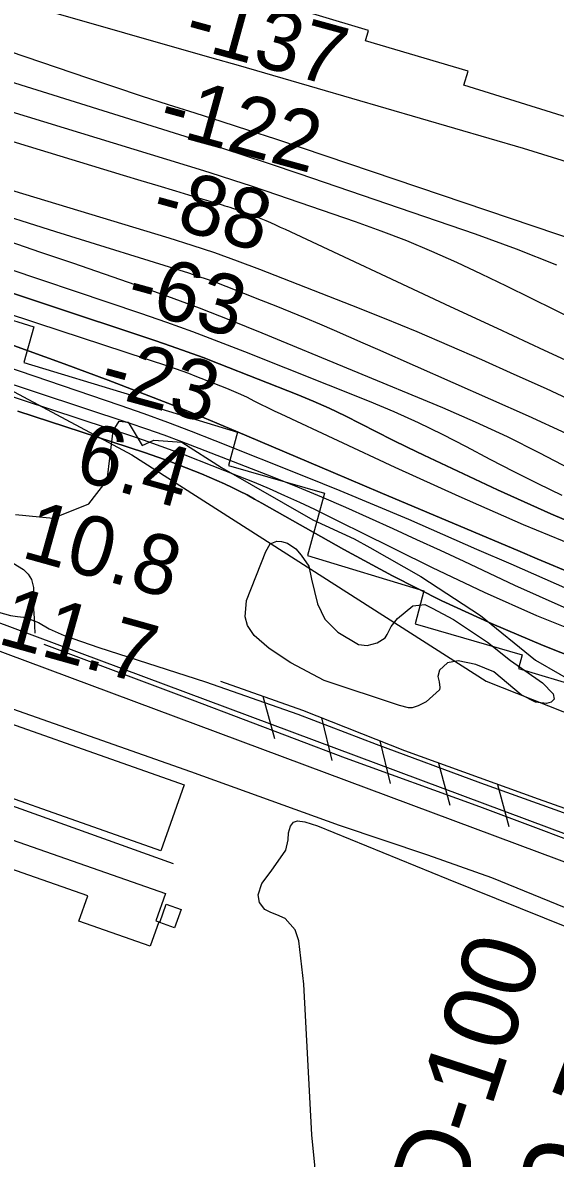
# Model space of a CAD drawing. Extents: x 3715084 to 3753216, y 488173 to 513963.
# Drawn here: x 3726412 to 3727006, y 497978 to 499247 of the extents above; entities that cross this region are included whole.
import ezdxf

# ---------------------------------------------------------------- set-up
doc = ezdxf.new("R2010")
doc.units = 0
for name, color, linetype in [('V-BLDG-OTLN', 7, 'Continuous'), ('V-FLOD-BASE', 7, 'Continuous'), ('V-LEVE-TOET', 7, 'Continuous'), ('V-RIVR-EDGE', 7, 'Continuous'), ('V-RIVR-RANG', 7, 'Continuous'), ('V-RIVR-RANG-IDEN', 7, 'Continuous'), ('V-ROAD-CNTR', 7, 'Continuous'), ('V-RRAP-FSHR', 7, 'Continuous'), ('V-RRAP-RVMT', 7, 'Continuous'), ('V-SITE-VEGE', 7, 'Continuous'), ('V-SURV-IDEN', 7, 'Continuous'), ('V-SURV-LINE', 7, 'Continuous'), ('V-TOPO-DPTH', 7, 'Continuous'), ('V-TOPO-MAJR', 7, 'Continuous'), ('V-TOPO-MINR', 7, 'Continuous'), ('V-TOPO-WATR', 7, 'Continuous')]:
    doc.layers.add(name, color=color, linetype=linetype)

msp = doc.modelspace()

# ---------------------------------------------------------------- linework, layer by layer
at = {"layer": 'V-BLDG-OTLN'}
for points in [[(3726309.3, 498495.2), (3726591.9, 498395.2), (3726565.9, 498321.6), (3726283.2, 498421.5)], [(3726554.1, 498215), (3726474.5, 498242.9), (3726484.5, 498271.3), (3726389.8, 498304.5), (3726400.1, 498333.9), (3726571.2, 498273.9), (3726560.4, 498243.1), (3726563.6, 498242)], [(3726572.1, 498261.8), (3726588.6, 498256), (3726581.4, 498235.4), (3726564.9, 498241.3)]]:
    msp.add_lwpolyline(points, close=True, dxfattribs=at)
at = {"layer": 'V-FLOD-BASE'}
msp.add_lwpolyline([(3726435.3, 498552.5), (3726601, 498490.1), (3726771.9, 498425.4), (3726921.7, 498371.2), (3727078.5, 498312.3), (3727260.6, 498243.5), (3727360.9, 498203.8), (3727504.7, 498147.2), (3727592.6, 498115.2), (3727705.1, 498073.2), (3727781.8, 498047), (3727820.7, 498036.5), (3727846.6, 498030.7), (3727871.9, 498027.3), (3727937.3, 498021), (3728099.8, 498012.2), (3728258.8, 498002.8)], dxfattribs=at)
at = {"layer": 'V-LEVE-TOET'}
for points in [[(3725953.9, 498750.4), (3725975.8, 498740.8), (3726002.6, 498731.4), (3726033, 498720.9), (3726090.4, 498697.5), (3726197.3, 498655.1), (3726292.1, 498620.8), (3726384.3, 498588.2), (3726398.1, 498584.4), (3726406.1, 498583.3), (3726412.7, 498582.5), (3726416.3, 498581.6)], [(3725958.4, 498636), (3725987.9, 498628), (3726077.6, 498597.4), (3726210.5, 498550.6), (3726367.3, 498491.9), (3726599, 498410), (3726765.2, 498350.1), (3726863.8, 498316.9), (3726935.1, 498291.6), (3727054.7, 498243), (3727151.8, 498206.2), (3727209, 498188.4), (3727242.1, 498172.1), (3727277, 498151.6), (3727309.7, 498134.7), (3727402.2, 498100.1), (3727510.5, 498069), (3727562.5, 498053.8), (3727581.7, 498047.1), (3727583, 498046.7)], [(3726416.3, 498581.6), (3726417.9, 498581), (3726429.4, 498576.8), (3726441.2, 498569.7), (3726458, 498562.2), (3726496.6, 498548.9), (3726615.9, 498510.5), (3726719.1, 498474.2), (3726806.4, 498440.7), (3726923, 498397.5), (3727049.3, 498352), (3727184.7, 498300.4), (3727316.2, 498249.8), (3727404.3, 498215.2), (3727526.4, 498167.7), (3727549, 498158.9)]]:
    msp.add_lwpolyline(points, dxfattribs=at)
at = {"layer": 'V-RIVR-EDGE'}
msp.add_lwpolyline([(3726403.8, 498697.5), (3726445.8, 498693.2), (3726485.5, 498709.3), (3726506, 498735.7), (3726512.7, 498790.9), (3726519.3, 498801.7), (3726529.5, 498800.5), (3726545.1, 498774.6), (3726558.3, 498780.6), (3726589.5, 498778.1), (3726633.9, 498749.8), (3726735.8, 498691.3), (3726781.9, 498670.2), (3726799.3, 498660.5), (3726856.3, 498628), (3726922.8, 498584.6), (3726984.5, 498534.6), (3727038.5, 498503.2)], dxfattribs=at)
at = {"layer": 'V-ROAD-CNTR'}
for points in [[(3726360.1, 498667.8), (3726412.7, 498635.9), (3726418, 498630.8), (3726421.5, 498624.6), (3726423.7, 498615.7), (3726423.6, 498597.1), (3726424.6, 498581.1), (3726425.4, 498564.7)], [(3725893.8, 498553.5), (3726579.6, 498307.2)]]:
    msp.add_lwpolyline(points, dxfattribs=at)
at = {"layer": 'V-RRAP-FSHR'}
for p, q in [((3726679.8, 498494.2), (3726693, 498447.1)), ((3726745.5, 498470.1), (3726756.8, 498422.6)), ((3726810.6, 498444.3), (3726821.9, 498396.8)), ((3726876.1, 498419.6), (3726888.8, 498372.5)), ((3726941.9, 498395.8), (3726954.7, 498348.7))]:
    msp.add_line(p, q, dxfattribs=at)
for points in [[(3719778.9, 501659.5), (3719780.9, 501658.9), (3720162.1, 501439.6), (3720517.2, 501248), (3721025.7, 501011.2), (3721396.9, 500844.8), (3721781.4, 500671.7), (3722343.7, 500424.7), (3722591.4, 500331.7), (3722936.5, 500157.7), (3723365.3, 499935.7), (3724002.2, 499670.3), (3724701.9, 499359), (3725287.2, 499128.8), (3725832.9, 499021), (3726260.1, 498910.4), (3726533.7, 498764.1), (3726929.4, 498511.1), (3727309.4, 498360.7), (3727495.4, 498332.2), (3727633.2, 498290.4), (3727809.2, 498206.8), (3728004.4, 498122.8), (3728249.6, 498078.8)], [(3727308.7, 498256.8), (3727263.5, 498272.8), (3727136.8, 498326.2), (3726987.6, 498379.3), (3726838.5, 498433.2), (3726724.4, 498478.5), (3726632.9, 498510.6)]]:
    msp.add_lwpolyline(points, dxfattribs=at)
at = {"layer": 'V-RRAP-RVMT'}
for p, q in [((3726797.8, 499238.2), (3726677.2, 499274.9)), ((3726794.5, 499226.9), (3726797.8, 499238.2)), ((3726909.1, 499192.7), (3726794.5, 499226.9)), ((3726904.2, 499177.2), (3726909.1, 499192.7)), ((3727031, 499137.7), (3726904.2, 499177.2)), ((3726305.1, 498943.3), (3726424.2, 498907.3)), ((3726424.2, 498907.3), (3726413.2, 498867.1)), ((3726413.2, 498867.1), (3726533.3, 498830.9)), ((3726533.3, 498830.9), (3726531.9, 498825.8)), ((3726531.9, 498825.8), (3726651.6, 498789.5)), ((3726651.6, 498789.5), (3726641.5, 498752.3)), ((3726641.5, 498752.3), (3726748.7, 498721.4)), ((3726748.7, 498721.4), (3726729.7, 498651.5)), ((3726729.7, 498651.5), (3726859.7, 498612)), ((3726859.7, 498612), (3726849.8, 498575.3)), ((3726849.8, 498575.3), (3726969.6, 498540.7)), ((3726969.6, 498540.7), (3726965.5, 498525.3)), ((3726965.5, 498525.3), (3727039.2, 498503))]:
    msp.add_line(p, q, dxfattribs=at)
at = {"layer": 'V-SITE-VEGE'}
msp.add_lwpolyline([(3726877.3, 498501.6), (3726862.4, 498488.2), (3726853.3, 498483.4), (3726846.5, 498481.4), (3726842.7, 498481.2), (3726832.3, 498483.9), (3726748.4, 498511.8), (3726711.1, 498531.7), (3726687, 498547.6), (3726670.2, 498562.3), (3726662.9, 498573.5), (3726660.1, 498583), (3726661.8, 498601.1), (3726683.2, 498656), (3726687.9, 498664.5), (3726695.6, 498667.7), (3726700.7, 498667.1), (3726707.4, 498665.3), (3726716.9, 498659.1), (3726722.7, 498652), (3726731.2, 498639.6), (3726734.4, 498625.2), (3726740.8, 498597.7), (3726749.1, 498580.4), (3726763.6, 498566), (3726786.7, 498552.1), (3726796.3, 498551), (3726807.4, 498553.8), (3726816.6, 498559.5), (3726818.8, 498563.3), (3726823.3, 498572.2), (3726830.3, 498581), (3726847.2, 498595.3), (3726860.6, 498596.7), (3726868.9, 498592.6), (3726892.6, 498580.1), (3726930.7, 498554.8), (3726956.6, 498534.4), (3726992, 498509.1), (3727004.2, 498496.9), (3727005, 498491.2), (3727001.9, 498487.5), (3726996.6, 498486.3), (3726984.2, 498487.6), (3726968.2, 498496), (3726937.7, 498521.7), (3726917.8, 498529.9), (3726897.9, 498533.8), (3726885.9, 498531.8), (3726877.2, 498523.5), (3726875.1, 498516.4), (3726876.7, 498510.3), (3726877.7, 498504)], close=True, dxfattribs=at)
msp.add_lwpolyline([(3726745.2, 497898.8), (3726734.7, 498004), (3726725.6, 498172.4), (3726720.1, 498220.8), (3726715.9, 498233.4), (3726704.9, 498246), (3726695.6, 498250.1), (3726688.7, 498252.5), (3726682, 498256), (3726676.2, 498263.8), (3726674.8, 498272.5), (3726678.7, 498285), (3726689.3, 498298.8), (3726705.4, 498322.3), (3726708.3, 498333.7), (3726708.5, 498341.6), (3726710.8, 498348.9), (3726714.3, 498353.5), (3726718.7, 498354.9), (3726726.7, 498353.9), (3726741.1, 498349.6), (3726886.7, 498290), (3727101.2, 498203.5)], dxfattribs=at)
at = {"layer": 'V-SURV-LINE'}
for points in [[(3725402.7, 498943.3), (3727093.5, 498312.2)], [(3727083, 498284.1), (3725392.3, 498915.2)]]:
    msp.add_lwpolyline(points, dxfattribs=at)
at = {"layer": 'V-TOPO-DPTH'}
for points in [[(3727029, 498630), (3726986.2, 498648), (3726967.3, 498655.9), (3726915.1, 498677.9), (3726862.9, 498700), (3726810.8, 498722.1), (3726758.6, 498744.3), (3726649.9, 498790.6), (3726614.4, 498805.5), (3726578.8, 498819.9), (3726543, 498833.9), (3726507, 498847.4), (3726458, 498865.6), (3726397.3, 498887.7), (3726336.5, 498909.3), (3726275.4, 498930.2), (3726214.2, 498950.8), (3725686.5, 499124.4), (3725658, 499134), (3725629.5, 499144), (3725601.2, 499154.3), (3725573, 499165), (3725377.1, 499241)], [(3727029, 498630), (3726986.2, 498648), (3726967.3, 498655.9), (3726915.1, 498677.9), (3726862.9, 498700), (3726810.8, 498722.1), (3726758.6, 498744.3), (3726649.9, 498790.6), (3726614.4, 498805.5), (3726578.8, 498819.9), (3726543, 498833.9), (3726507, 498847.4), (3726458, 498865.6), (3726397.3, 498887.7), (3726336.5, 498909.3), (3726275.4, 498930.2), (3726214.2, 498950.8), (3725686.5, 499124.4), (3725658, 499134), (3725629.5, 499144), (3725601.2, 499154.3), (3725573, 499165), (3725377.1, 499241)], [(3727061.1, 498672.8), (3727001.3, 498698.3), (3726941.9, 498725), (3726859.5, 498763.7), (3726841.8, 498772.2), (3726824.2, 498780.8), (3726806.7, 498789.7), (3726789.3, 498798.7), (3726771.8, 498807.6), (3726754.1, 498816.1), (3726736.2, 498824), (3726718.1, 498831.5), (3726631, 498865.8), (3726613.2, 498872.7), (3726595.3, 498879.3), (3726577.4, 498885.7), (3726559.3, 498891.8), (3725816.5, 499139)], [(3727061.1, 498672.8), (3727001.3, 498698.3), (3726941.9, 498725), (3726859.5, 498763.7), (3726841.8, 498772.2), (3726824.2, 498780.8), (3726806.7, 498789.7), (3726789.3, 498798.7), (3726771.8, 498807.6), (3726754.1, 498816.1), (3726736.2, 498824), (3726718.1, 498831.5), (3726631, 498865.8), (3726613.2, 498872.7), (3726595.3, 498879.3), (3726577.4, 498885.7), (3726559.3, 498891.8), (3725816.5, 499139)], [(3725709.8, 499071.6), (3726530.2, 498799.9), (3726549.9, 498793.2), (3726569.5, 498786.3), (3726589.1, 498779.1), (3726608.5, 498771.7), (3726691.7, 498739.1), (3726718.7, 498728.3), (3726745.5, 498717.2), (3726772.2, 498705.6), (3726798.7, 498693.8), (3726825.1, 498681.8), (3726851.5, 498669.6), (3726877.9, 498657.4), (3726904.2, 498645.1), (3726961, 498618.6), (3727016, 498593.8)], [(3725709.8, 499071.6), (3726530.2, 498799.9), (3726549.9, 498793.2), (3726569.5, 498786.3), (3726589.1, 498779.1), (3726608.5, 498771.7), (3726691.7, 498739.1), (3726718.7, 498728.3), (3726745.5, 498717.2), (3726772.2, 498705.6), (3726798.7, 498693.8), (3726825.1, 498681.8), (3726851.5, 498669.6), (3726877.9, 498657.4), (3726904.2, 498645.1), (3726961, 498618.6), (3727016, 498593.8)], [(3726347.8, 498937.8), (3726428.3, 498911.3), (3726574.6, 498863.1), (3726582, 498860.6), (3726589.4, 498858), (3726596.8, 498855.2), (3726604.1, 498852.4), (3726639.4, 498838.5), (3726647.1, 498835.3), (3726654.8, 498832), (3726662.4, 498828.4), (3726669.9, 498824.6), (3726677.4, 498820.8), (3726685, 498817.1), (3726692.5, 498813.4), (3726700.1, 498809.8), (3726827.2, 498750.2), (3726898.7, 498717.7), (3726970.6, 498686.2), (3727043.3, 498656.4)], [(3726347.8, 498937.8), (3726428.3, 498911.3), (3726574.6, 498863.1), (3726582, 498860.6), (3726589.4, 498858), (3726596.8, 498855.2), (3726604.1, 498852.4), (3726639.4, 498838.5), (3726647.1, 498835.3), (3726654.8, 498832), (3726662.4, 498828.4), (3726669.9, 498824.6), (3726677.4, 498820.8), (3726685, 498817.1), (3726692.5, 498813.4), (3726700.1, 498809.8), (3726827.2, 498750.2), (3726898.7, 498717.7), (3726970.6, 498686.2), (3727043.3, 498656.4)], [(3727073.6, 498518.9), (3726993, 498551.1), (3726936, 498575.2), (3726879.7, 498600.8), (3726824.6, 498628.8), (3726770.2, 498658.2), (3726678.7, 498710.2), (3726670.5, 498714.7), (3726662.3, 498719.2), (3726654, 498723.5), (3726645.6, 498727.7), (3726637.2, 498731.7), (3726628.7, 498735.5), (3726620.1, 498739.2), (3726611.4, 498742.7), (3726577.3, 498756.1), (3726570, 498758.8), (3726562.7, 498761.5), (3726555.3, 498764.1), (3726547.9, 498766.6), (3726406.4, 498813)]]:
    msp.add_lwpolyline(points, dxfattribs=at)
at = {"layer": 'V-TOPO-MAJR'}
for points in [[(3726031.1, 499260.8), (3726139.6, 499227.1), (3726248.1, 499193.6), (3726356.7, 499160.3), (3726613.5, 499081.8), (3726631, 499076.3), (3726648.4, 499070.8), (3726665.8, 499065), (3726683.1, 499059.2), (3726783, 499024.8), (3726811.7, 499014.4), (3726840.2, 499003.5), (3726868.3, 498991.7), (3726896.2, 498979.3), (3726923.8, 498966.3), (3726951.4, 498953.1), (3726978.8, 498939.7), (3727006.1, 498926), (3727045.3, 498906.2)], [(3725591.6, 499253.3), (3725625.1, 499240.2), (3725658.6, 499227.3), (3725692.4, 499214.8), (3725726.2, 499202.6), (3725830.6, 499165.5), (3725916.8, 499135.2), (3726003.1, 499105.1), (3726089.5, 499075.4), (3726176, 499046), (3726543.2, 498922.4), (3726572.4, 498912.3), (3726601.5, 498901.9), (3726630.5, 498890.9), (3726659.3, 498879.7), (3726798.5, 498824.1), (3726826.1, 498812.5), (3726853.4, 498800.2), (3726880.3, 498787.1), (3726906.9, 498773.3), (3726933.4, 498759.2), (3726960, 498745.4), (3726986.9, 498732.1), (3727013.8, 498718.9)]]:
    msp.add_lwpolyline(points, dxfattribs=at)
at = {"layer": 'V-TOPO-MINR'}
for points in [[(3725245.4, 499590.8), (3725645.7, 499429.6), (3725682.4, 499415.1), (3725719.3, 499400.9), (3725756.3, 499387.2), (3725793.5, 499373.9), (3725830.8, 499360.9), (3725868.2, 499348.3), (3725905.8, 499336), (3725943.4, 499324), (3726592.7, 499120.3), (3726624.6, 499110.2), (3726656.5, 499099.8), (3726688.2, 499089.3), (3726719.9, 499078.5), (3726916.9, 499010.9), (3726962.6, 498994.2), (3727007.9, 498976.3)], [(3725373.4, 499579.9), (3725463.2, 499544.7), (3725553.2, 499510.1), (3725691.8, 499457.2), (3725712.7, 499449.4), (3725733.5, 499441.7), (3725754.5, 499434.3), (3725775.5, 499427), (3726484.2, 499185.3), (3726514.1, 499175.3), (3726544, 499165.4), (3726574, 499155.7), (3726604, 499146.2), (3726634, 499136.6), (3726664, 499127), (3726693.9, 499117.1), (3726723.8, 499107.1), (3727059.7, 498993.4)], [(3725378.1, 499360), (3725474.1, 499323.1), (3725622, 499266.6), (3725644.2, 499258.2), (3725666.6, 499250.1), (3725689, 499242.1), (3725711.5, 499234.4), (3726396.1, 499002.7), (3726431.6, 498990.6), (3726467.2, 498978.5), (3726502.7, 498966.3), (3726538.2, 498954), (3726573.6, 498941.4), (3726608.8, 498928.3), (3726643.8, 498914.7), (3726678.6, 498900.6), (3726880.6, 498816.8), (3726916.9, 498801.1), (3726952.8, 498784.5), (3726988, 498766.8), (3727022.9, 498748.3)], [(3726135, 499347.8), (3726623, 499207.9), (3726652.4, 499199.4), (3726681.7, 499191), (3726711.1, 499182.5), (3726740.4, 499173.9), (3726970.5, 499106.9), (3727046.2, 499083.2)], [(3725754.2, 499311.9), (3726524.1, 499076.6), (3726543.5, 499070.7), (3726562.8, 499064.9), (3726582.2, 499059), (3726601.6, 499053.2), (3726634.5, 499043.4), (3726637.4, 499042.5), (3726640.3, 499041.6), (3726643.2, 499040.7), (3726646.1, 499039.7), (3726661.2, 499034.5), (3726666.8, 499032.5), (3726672.3, 499030.4), (3726677.8, 499028.2), (3726683.2, 499026), (3726688.6, 499023.6), (3726694, 499021.2), (3726699.4, 499018.7), (3726704.7, 499016.3), (3726889.2, 498930), (3726941.6, 498905.5), (3726994, 498881.1), (3727046.4, 498856.8)], [(3725689.6, 499279.4), (3725791.2, 499246.4), (3725847.7, 499228.3), (3725904.4, 499210.3), (3725961.1, 499192.7), (3726018, 499175.3), (3726575, 499006.6), (3726600.6, 498998.5), (3726626, 498990.1), (3726651.2, 498981), (3726676.2, 498971.5), (3726778.7, 498931.4), (3726815.3, 498916.8), (3726851.8, 498901.8), (3726888.1, 498886.4), (3726924.2, 498870.6), (3726960.2, 498854.4), (3726996.1, 498838.1), (3727031.8, 498821.4)], [(3725700.3, 499257.7), (3726109.6, 499122.5), (3726194.1, 499094.9), (3726278.7, 499067.5), (3726363.4, 499040.5), (3726448.2, 499013.7), (3726596.8, 498967.3), (3726607.3, 498963.9), (3726617.8, 498960.3), (3726628.1, 498956.6), (3726638.5, 498952.6), (3726678.1, 498937.1), (3726694.5, 498930.6), (3726710.8, 498924), (3726727, 498917.2), (3726743.3, 498910.4), (3726759.4, 498903.4), (3726775.6, 498896.4), (3726791.7, 498889.3), (3726807.8, 498882.2), (3726976.1, 498807.7), (3727018.3, 498788.2)], [(3725377.1, 499241), (3725573, 499165), (3725601.2, 499154.3), (3725629.5, 499144), (3725658, 499134), (3725686.5, 499124.4), (3726214.2, 498950.8), (3726275.4, 498930.2), (3726336.5, 498909.3), (3726397.3, 498887.7), (3726458, 498865.6), (3726507, 498847.4), (3726543, 498833.9), (3726578.8, 498819.9), (3726614.4, 498805.5), (3726649.9, 498790.6), (3726758.6, 498744.3), (3726810.8, 498722.1), (3726862.9, 498700), (3726915.1, 498677.9), (3726967.3, 498655.9), (3726986.2, 498648), (3727029, 498630)], [(3725816.5, 499139), (3726559.3, 498891.8), (3726577.4, 498885.7), (3726595.3, 498879.3), (3726613.2, 498872.7), (3726631, 498865.8), (3726718.1, 498831.5), (3726736.2, 498824), (3726754.1, 498816.1), (3726771.8, 498807.6), (3726789.3, 498798.7), (3726806.7, 498789.7), (3726824.2, 498780.8), (3726841.8, 498772.2), (3726859.5, 498763.7), (3726941.9, 498725), (3727001.3, 498698.3), (3727061.1, 498672.8)], [(3725709.8, 499071.6), (3726530.2, 498799.9), (3726549.9, 498793.2), (3726569.5, 498786.3), (3726589.1, 498779.1), (3726608.5, 498771.7), (3726691.7, 498739.1), (3726718.7, 498728.3), (3726745.5, 498717.2), (3726772.2, 498705.6), (3726798.7, 498693.8), (3726825.1, 498681.8), (3726851.5, 498669.6), (3726877.9, 498657.4), (3726904.2, 498645.1), (3726961, 498618.6), (3727016, 498593.8)], [(3726086.7, 498967.4), (3726520.2, 498819.5), (3726546.9, 498810.1), (3726573.5, 498800.5), (3726599.9, 498790.5), (3726626.2, 498780.2), (3726727.2, 498739.8), (3726765.7, 498724.2), (3726804.1, 498708.3), (3726842.4, 498692), (3726880.5, 498675.5), (3726918.6, 498658.8), (3726956.7, 498642.1), (3726994.7, 498625.4), (3727032.8, 498608.7)], [(3726347.8, 498937.8), (3726428.3, 498911.3), (3726574.6, 498863.1), (3726582, 498860.6), (3726589.4, 498858), (3726596.8, 498855.2), (3726604.1, 498852.4), (3726639.4, 498838.5), (3726647.1, 498835.3), (3726654.8, 498832), (3726662.4, 498828.4), (3726669.9, 498824.6), (3726677.4, 498820.8), (3726685, 498817.1), (3726692.5, 498813.4), (3726700.1, 498809.8), (3726827.2, 498750.2), (3726898.7, 498717.7), (3726970.6, 498686.2), (3727043.3, 498656.4)], [(3726156.6, 498909.2), (3726539, 498783.3), (3726552.6, 498778.7), (3726566.1, 498773.9), (3726579.5, 498769), (3726592.9, 498763.9), (3726653, 498740.3), (3726670.1, 498733.4), (3726687.1, 498726.3), (3726703.9, 498718.8), (3726720.7, 498711.1), (3726737.4, 498703.2), (3726754, 498695.2), (3726770.5, 498687.1), (3726787.1, 498678.9), (3726869, 498638), (3726926.9, 498610.5), (3726985.5, 498584.4), (3727045, 498560.7)]]:
    msp.add_lwpolyline(points, dxfattribs=at)
at = {"layer": 'V-TOPO-WATR'}
msp.add_lwpolyline([(3726406.4, 498813), (3726547.9, 498766.6), (3726555.3, 498764.1), (3726562.7, 498761.5), (3726570, 498758.8), (3726577.3, 498756.1), (3726611.4, 498742.7), (3726620.1, 498739.2), (3726628.7, 498735.5), (3726637.2, 498731.7), (3726645.6, 498727.7), (3726654, 498723.5), (3726662.3, 498719.2), (3726670.5, 498714.7), (3726678.7, 498710.2), (3726770.2, 498658.2), (3726824.6, 498628.8), (3726879.7, 498600.8), (3726936, 498575.2), (3726993, 498551.1), (3727073.6, 498518.9)], dxfattribs=at)

# ---------------------------------------------------------------- texts
at = {"layer": 'V-RIVR-RANG'}
for s, rotation, p in [('-137', 344.6519, (3726589.4, 499222)), ('-122', 344.6519, (3726560.7, 499126.2)), ('-88', 344.6519, (3726552.8, 499024.6)), ('-63', 344.6519, (3726524.5, 498928.7)), ('-23', 344.6519, (3726494.8, 498833.2)), ('6.4', 344.3683, (3726467.3, 498737.5)), ('10.8', 344.3683, (3726408.6, 498650)), ('11.7', 344.3683, (3726381.9, 498553.7))]:
    msp.add_text(s, height=67, rotation=rotation, dxfattribs=at).set_placement(p)
at = {"layer": 'V-RIVR-RANG-IDEN'}
msp.add_text('D-100', height=83, rotation=72.0263, dxfattribs=at).set_placement((3726898.8, 497922.4))
at = {"layer": 'V-SURV-IDEN'}
msp.add_text('55+29.7', height=100, rotation=68.825, dxfattribs=at).set_placement((3726944.9, 497624.7))

doc.saveas('drawing.dxf')
